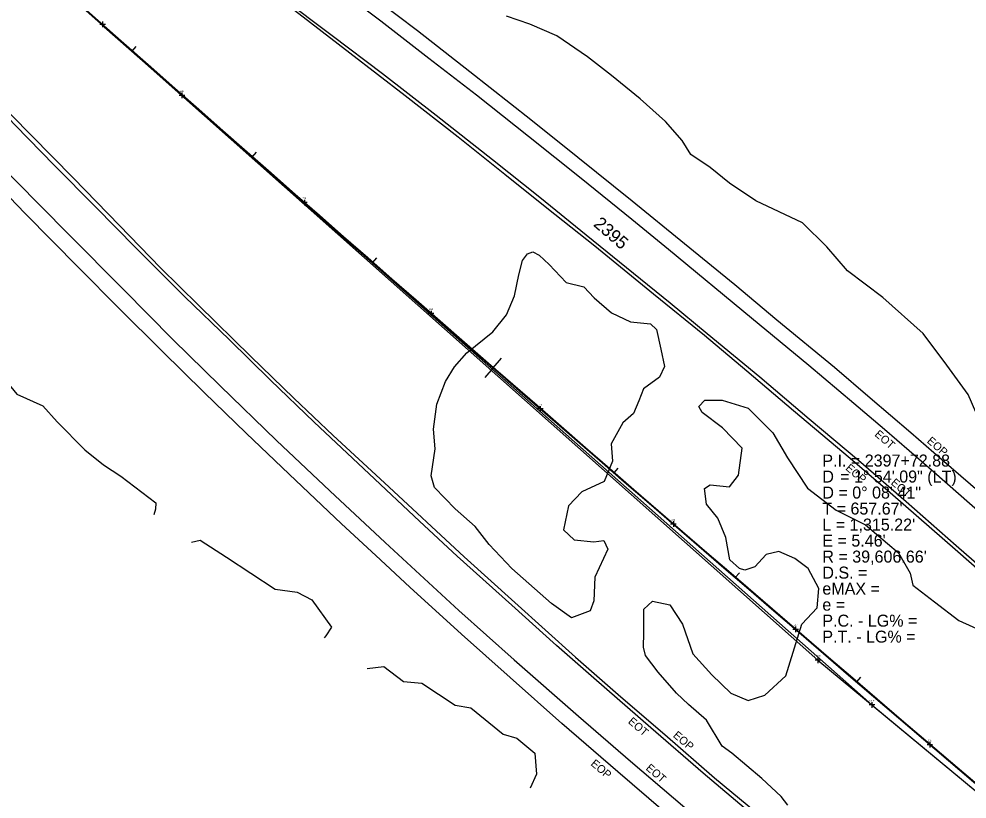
# Model space of a CAD drawing. Extents: x 2076109 to 2080761, y 592812 to 596750.
# Drawn here: x 2077921 to 2078513, y 594710 to 595198 of the extents above; entities that cross this region are included whole.
import ezdxf

# ---------------------------------------------------------------- set-up
doc = ezdxf.new("R2010")
doc.units = 0
for name, color, linetype in [('Default', 7, 'Continuous'), ('RD_EX_Misc', 7, 'Continuous'), ('RD_EX_Misc_txCode', 7, 'Continuous'), ('RD_EX_Road', 7, 'Continuous'), ('RD_EX_Road_txCode', 7, 'Continuous'), ('RD_EX_VEG', 7, 'Continuous'), ('RD_HC_Cl', 7, 'Continuous'), ('RD_HC_Data', 7, 'Continuous'), ('RD_HC_Data_Tic', 7, 'Continuous'), ('RD_HC_TX_Sta50', 7, 'Continuous')]:
    doc.layers.add(name, color=color, linetype=linetype)

msp = doc.modelspace()

# ---------------------------------------------------------------- linework, layer by layer
at = {"layer": 'Default'}
for p, q in [((2077364.31, 595733.06), (2078453.96, 594769.07)), ((2077364.31, 595733.06), (2078453.96, 594769.07)), ((2077404.89, 595698.18), (2078420.27, 594797.03)), ((2077404.89, 595698.18), (2078420.27, 594797.03)), ((2077975.19, 595194.17), (2077971.69, 595194.17)), ((2077975.19, 595194.17), (2077971.69, 595194.17)), ((2077973.44, 595195.92), (2077973.44, 595192.42)), ((2077973.44, 595195.92), (2077973.44, 595192.42)), ((2078024.71, 595149.76), (2078021.21, 595149.76)), ((2078024.71, 595149.76), (2078021.21, 595149.76)), ((2078022.96, 595151.51), (2078022.96, 595148.01)), ((2078022.96, 595151.51), (2078022.96, 595148.01)), ((2078099.45, 595084.6), (2078099.45, 595081.1)), ((2078099.45, 595084.6), (2078099.45, 595081.1)), ((2078101.2, 595082.85), (2078097.7, 595082.85)), ((2078101.2, 595082.85), (2078097.7, 595082.85)), ((2078180.32, 595013.58), (2078176.82, 595013.58)), ((2078180.32, 595013.58), (2078176.82, 595013.58)), ((2078178.57, 595015.33), (2078178.57, 595011.83)), ((2078178.57, 595015.33), (2078178.57, 595011.83)), ((2078248.58, 594953.95), (2078245.08, 594953.95)), ((2078248.58, 594953.95), (2078245.08, 594953.95)), ((2078246.83, 594955.7), (2078246.83, 594952.2)), ((2078246.83, 594955.7), (2078246.83, 594952.2)), ((2078329.94, 594883.79), (2078329.94, 594880.29)), ((2078329.94, 594883.79), (2078329.94, 594880.29)), ((2078331.69, 594882.04), (2078328.19, 594882.04)), ((2078331.69, 594882.04), (2078328.19, 594882.04)), ((2078406.28, 594818.04), (2078406.28, 594814.54)), ((2078406.28, 594818.04), (2078406.28, 594814.54)), ((2078408.03, 594816.29), (2078404.53, 594816.29)), ((2078408.03, 594816.29), (2078404.53, 594816.29)), ((2078422.02, 594797.03), (2078418.52, 594797.03)), ((2078422.02, 594797.03), (2078418.52, 594797.03)), ((2078422.02, 594797.03), (2078418.52, 594797.03)), ((2078422.02, 594797.03), (2078418.52, 594797.03)), ((2078420.27, 594798.78), (2078420.27, 594795.28)), ((2078420.27, 594798.78), (2078420.27, 594795.28)), ((2078420.27, 594798.78), (2078420.27, 594795.28)), ((2078420.27, 594798.78), (2078420.27, 594795.28)), ((2078420.27, 594797.03), (2079388.11, 593993.88)), ((2078420.27, 594797.03), (2079388.11, 593993.88)), ((2078453.96, 594770.82), (2078453.96, 594767.32)), ((2078453.96, 594770.82), (2078453.96, 594767.32)), ((2078453.96, 594770.82), (2078453.96, 594767.32)), ((2078453.96, 594770.82), (2078453.96, 594767.32)), ((2078455.71, 594769.07), (2078452.21, 594769.07)), ((2078455.71, 594769.07), (2078452.21, 594769.07)), ((2078455.71, 594769.07), (2078452.21, 594769.07)), ((2078455.71, 594769.07), (2078452.21, 594769.07)), ((2078453.96, 594769.07), (2079386.42, 593995.29)), ((2078453.96, 594769.07), (2079386.42, 593995.29)), ((2078491.88, 594744.27), (2078488.38, 594744.27)), ((2078491.88, 594744.27), (2078488.38, 594744.27)), ((2078490.13, 594746.02), (2078490.13, 594742.52)), ((2078490.13, 594746.02), (2078490.13, 594742.52))]:
    msp.add_line(p, q, dxfattribs=at)
for centre, radius, start, end in [((2104218.85, 624856.19), 39606.66, 228.410497, 230.313125), ((2104218.85, 624856.19), 39606.66, 228.410497, 230.313125), ((2104856.13, 625580.79), 40571.24, 228.501187, 230.313123), ((2104856.13, 625580.79), 40571.24, 228.501187, 230.313123)]:
    msp.add_arc(centre, radius, start, end, dxfattribs=at)
at = {"layer": 'RD_EX_Misc'}
for points in [[(2078547.92, 594865.99), (2078523.55, 594887.48), (2078492.6, 594914.58), (2078461.72, 594941.03), (2078442.57, 594957.36), (2078414.55, 594981.01), (2078378.82, 595010.71), (2078326.85, 595053.48), (2078303.99, 595072.33), (2078272.31, 595097.98), (2078239.48, 595124.07), (2078206.94, 595149.86), (2078177.28, 595172.92), (2078147.14, 595196.07), (2078111.31, 595223.33), (2078077.15, 595249.21), (2078034.45, 595281.85), (2078002.89, 595305.93), (2077949.74, 595346.22)], [(2078547.92, 594865.99), (2078523.55, 594887.48), (2078492.6, 594914.58), (2078461.72, 594941.03), (2078442.57, 594957.36), (2078414.55, 594981.01), (2078378.82, 595010.71), (2078326.85, 595053.48), (2078303.99, 595072.33), (2078272.31, 595097.98), (2078239.48, 595124.07), (2078206.94, 595149.86), (2078177.28, 595172.92), (2078147.14, 595196.07), (2078111.31, 595223.33), (2078077.15, 595249.21), (2078034.45, 595281.85), (2078002.89, 595305.93), (2077949.74, 595346.22)], [(2077948.94, 595314.49), (2077983.17, 595288.64), (2078019.77, 595260.72), (2078053.66, 595234.89), (2078085.02, 595211.3), (2078116.87, 595187.29), (2078148.23, 595163.42), (2078181.8, 595137.39), (2078217.02, 595109.84), (2078246.55, 595086.19), (2078275.57, 595062.75), (2078305.1, 595038.73), (2078327.94, 595020.19), (2078351.12, 595001.07), (2078383.9, 594974.11), (2078414.8, 594947.69), (2078445.52, 594921.98), (2078475.27, 594896.22), (2078506.67, 594868.78), (2078527.36, 594850.61)], [(2077948.94, 595314.49), (2077983.17, 595288.64), (2078019.77, 595260.72), (2078053.66, 595234.89), (2078085.02, 595211.3), (2078116.87, 595187.29), (2078148.23, 595163.42), (2078181.8, 595137.39), (2078217.02, 595109.84), (2078246.55, 595086.19), (2078275.57, 595062.75), (2078305.1, 595038.73), (2078327.94, 595020.19), (2078351.12, 595001.07), (2078383.9, 594974.11), (2078414.8, 594947.69), (2078445.52, 594921.98), (2078475.27, 594896.22), (2078506.67, 594868.78), (2078527.36, 594850.61)], [(2077812.69, 595205.74), (2077860.4, 595156.88), (2077885.59, 595131.05), (2077918.9, 595096.93), (2077951.97, 595063.28), (2077986.45, 595028.54), (2078017.36, 594997.38), (2078046.97, 594968.42), (2078082.15, 594934.23), (2078115.46, 594902.77), (2078149.86, 594870.52), (2078195.91, 594828.19), (2078230.53, 594797.18), (2078270.78, 594762.03), (2078303.08, 594733.97), (2078349.76, 594694.22), (2078384.22, 594665.44)], [(2077812.69, 595205.74), (2077860.4, 595156.88), (2077885.59, 595131.05), (2077918.9, 595096.93), (2077951.97, 595063.28), (2077986.45, 595028.54), (2078017.36, 594997.38), (2078046.97, 594968.42), (2078082.15, 594934.23), (2078115.46, 594902.77), (2078149.86, 594870.52), (2078195.91, 594828.19), (2078230.53, 594797.18), (2078270.78, 594762.03), (2078303.08, 594733.97), (2078349.76, 594694.22), (2078384.22, 594665.44)], [(2078402.59, 594681.19), (2078376.88, 594702.6), (2078348.66, 594726.55), (2078315.84, 594754.87), (2078280.23, 594785.85), (2078257.02, 594806.28), (2078229.05, 594831.44), (2078194.83, 594862.11), (2078171.35, 594883.78), (2078139.88, 594913.53), (2078105.56, 594945.66), (2078078.38, 594971.9), (2078052.44, 594997.28), (2078024.89, 595024.02), (2077994.25, 595054.58), (2077968.94, 595080.1), (2077943.23, 595106.24), (2077919, 595131.04), (2077898.15, 595152.63), (2077868.92, 595182.73), (2077850.7, 595201.63)], [(2078402.59, 594681.19), (2078376.88, 594702.6), (2078348.66, 594726.55), (2078315.84, 594754.87), (2078280.23, 594785.85), (2078257.02, 594806.28), (2078229.05, 594831.44), (2078194.83, 594862.11), (2078171.35, 594883.78), (2078139.88, 594913.53), (2078105.56, 594945.66), (2078078.38, 594971.9), (2078052.44, 594997.28), (2078024.89, 595024.02), (2077994.25, 595054.58), (2077968.94, 595080.1), (2077943.23, 595106.24), (2077919, 595131.04), (2077898.15, 595152.63), (2077868.92, 595182.73), (2077850.7, 595201.63)]]:
    msp.add_lwpolyline(points, dxfattribs=at)
at = {"layer": 'RD_EX_Road'}
for points in [[(2078558.22, 594869.34), (2078530.91, 594893.2), (2078521.67, 594901.52), (2078497.33, 594922.45), (2078478.18, 594939.06), (2078452.82, 594960.76), (2078430.65, 594979.76), (2078394.66, 595009.49), (2078368.3, 595031.41), (2078336.81, 595057.13), (2078304.21, 595083.71), (2078270.36, 595111.03), (2078240.97, 595134.51), (2078202.89, 595164.59), (2078170.15, 595190.09), (2078144.69, 595209.49), (2078118.53, 595229.54), (2078095.36, 595247.04), (2078066.11, 595268.74), (2078042.16, 595286.91), (2078005.38, 595314.83), (2077980.94, 595333.23), (2077970.95, 595340.99)], [(2078558.22, 594869.34), (2078530.91, 594893.2), (2078521.67, 594901.52), (2078497.33, 594922.45), (2078478.18, 594939.06), (2078452.82, 594960.76), (2078430.65, 594979.76), (2078394.66, 595009.49), (2078368.3, 595031.41), (2078336.81, 595057.13), (2078304.21, 595083.71), (2078270.36, 595111.03), (2078240.97, 595134.51), (2078202.89, 595164.59), (2078170.15, 595190.09), (2078144.69, 595209.49), (2078118.53, 595229.54), (2078095.36, 595247.04), (2078066.11, 595268.74), (2078042.16, 595286.91), (2078005.38, 595314.83), (2077980.94, 595333.23), (2077970.95, 595340.99)], [(2077952.98, 595309.03), (2077986.31, 595283.86), (2078021.67, 595256.91), (2078055.44, 595231.27), (2078085.91, 595208.57), (2078127.78, 595176.36), (2078162.35, 595149.71), (2078195.51, 595123.85), (2078224.64, 595100.6), (2078250.87, 595079.67), (2078280.9, 595055.74), (2078317.56, 595025.94), (2078349.29, 594999.96), (2078375.78, 594977.71), (2078405, 594953.04), (2078440.35, 594923.16), (2078465.28, 594901.73), (2078507.59, 594865.01), (2078528.26, 594846.85)], [(2077952.98, 595309.03), (2077986.31, 595283.86), (2078021.67, 595256.91), (2078055.44, 595231.27), (2078085.91, 595208.57), (2078127.78, 595176.36), (2078162.35, 595149.71), (2078195.51, 595123.85), (2078224.64, 595100.6), (2078250.87, 595079.67), (2078280.9, 595055.74), (2078317.56, 595025.94), (2078349.29, 594999.96), (2078375.78, 594977.71), (2078405, 594953.04), (2078440.35, 594923.16), (2078465.28, 594901.73), (2078507.59, 594865.01), (2078528.26, 594846.85)], [(2077854.91, 595200.66), (2077877.75, 595177.1), (2077904.18, 595149.75), (2077928.86, 595124.99), (2077955.23, 595098.06), (2077983.95, 595068.48), (2078009.65, 595042.17), (2078033.35, 595018.7), (2078066.05, 594986.67), (2078092.96, 594960.65), (2078117.38, 594937.31), (2078149.5, 594907.79), (2078199.33, 594861.59), (2078231.01, 594833.12), (2078268.85, 594798.92), (2078297.2, 594774.26), (2078324.57, 594750.57), (2078355.73, 594723.65), (2078382.01, 594701.63), (2078403.91, 594683.55)], [(2077854.91, 595200.66), (2077877.75, 595177.1), (2077904.18, 595149.75), (2077928.86, 595124.99), (2077955.23, 595098.06), (2077983.95, 595068.48), (2078009.65, 595042.17), (2078033.35, 595018.7), (2078066.05, 594986.67), (2078092.96, 594960.65), (2078117.38, 594937.31), (2078149.5, 594907.79), (2078199.33, 594861.59), (2078231.01, 594833.12), (2078268.85, 594798.92), (2078297.2, 594774.26), (2078324.57, 594750.57), (2078355.73, 594723.65), (2078382.01, 594701.63), (2078403.91, 594683.55)], [(2078373.49, 594660.86), (2078350.79, 594679.96), (2078323.49, 594703.04), (2078295.32, 594727.33), (2078260.34, 594757.49), (2078227.96, 594786.32), (2078197.61, 594813.23), (2078165.4, 594842.74), (2078144.08, 594862.48), (2078122.73, 594882.29), (2078089.93, 594913.22), (2078063.14, 594938.9), (2078036.94, 594964.31), (2078010.5, 594990.24), (2077983.8, 595016.72), (2077958.57, 595042.08), (2077925.08, 595076.09), (2077900.51, 595101.35), (2077873.61, 595129.01), (2077849.3, 595153.72), (2077820.29, 595183.84)], [(2078373.49, 594660.86), (2078350.79, 594679.96), (2078323.49, 594703.04), (2078295.32, 594727.33), (2078260.34, 594757.49), (2078227.96, 594786.32), (2078197.61, 594813.23), (2078165.4, 594842.74), (2078144.08, 594862.48), (2078122.73, 594882.29), (2078089.93, 594913.22), (2078063.14, 594938.9), (2078036.94, 594964.31), (2078010.5, 594990.24), (2077983.8, 595016.72), (2077958.57, 595042.08), (2077925.08, 595076.09), (2077900.51, 595101.35), (2077873.61, 595129.01), (2077849.3, 595153.72), (2077820.29, 595183.84)]]:
    msp.add_lwpolyline(points, dxfattribs=at)
at = {"layer": 'RD_EX_VEG'}
for points in [[(2078557.7, 594903.93), (2078543.39, 594912.86), (2078531.57, 594916.48), (2078520.77, 594933.39), (2078521.66, 594945.68), (2078514, 594963.05), (2078500.7, 594981.35), (2078485.99, 595001.02), (2078460.72, 595023.62), (2078438.61, 595040.22), (2078425.78, 595055.18), (2078410.65, 595070.25), (2078381.52, 595083.99), (2078365.03, 595095.08), (2078352.91, 595104.83), (2078340.83, 595112.9), (2078335.45, 595121.7), (2078324.96, 595133.57), (2078309.12, 595147.59), (2078291.24, 595162.24), (2078276.39, 595173.96), (2078257.26, 595186.92), (2078240.36, 595194.3), (2078225.66, 595199.27)], [(2078557.7, 594903.93), (2078543.39, 594912.86), (2078531.57, 594916.48), (2078520.77, 594933.39), (2078521.66, 594945.68), (2078514, 594963.05), (2078500.7, 594981.35), (2078485.99, 595001.02), (2078460.72, 595023.62), (2078438.61, 595040.22), (2078425.78, 595055.18), (2078410.65, 595070.25), (2078381.52, 595083.99), (2078365.03, 595095.08), (2078352.91, 595104.83), (2078340.83, 595112.9), (2078335.45, 595121.7), (2078324.96, 595133.57), (2078309.12, 595147.59), (2078291.24, 595162.24), (2078276.39, 595173.96), (2078257.26, 595186.92), (2078240.36, 595194.3), (2078225.66, 595199.27)], [(2077773.22, 595117.2), (2077791.56, 595101.41), (2077809.23, 595084.36), (2077830.79, 595059.77), (2077838.08, 595056.89), (2077849.16, 595042.68), (2077857.1, 595036.66), (2077867.15, 595031.61), (2077876.37, 595019.54), (2077892.53, 595000.28), (2077900.86, 594995.59), (2077906.78, 594987.42), (2077911.5, 594973.3), (2077919.86, 594963.24), (2077936.16, 594955.82), (2077945.1, 594946.01), (2077962.43, 594928.33), (2077974.01, 594919.03), (2077984.91, 594911.96), (2078006.62, 594895.34), (2078006.55, 594891.36), (2078005.4, 594887.74)], [(2077773.22, 595117.2), (2077791.56, 595101.41), (2077809.23, 595084.36), (2077830.79, 595059.77), (2077838.08, 595056.89), (2077849.16, 595042.68), (2077857.1, 595036.66), (2077867.15, 595031.61), (2077876.37, 595019.54), (2077892.53, 595000.28), (2077900.86, 594995.59), (2077906.78, 594987.42), (2077911.5, 594973.3), (2077919.86, 594963.24), (2077936.16, 594955.82), (2077945.1, 594946.01), (2077962.43, 594928.33), (2077974.01, 594919.03), (2077984.91, 594911.96), (2078006.62, 594895.34), (2078006.55, 594891.36), (2078005.4, 594887.74)], [(2078401.4, 594706.61), (2078397.2, 594711.83), (2078385.2, 594723.15), (2078366.44, 594738.92), (2078360.42, 594743.3), (2078350.66, 594759.51), (2078339.35, 594769.29), (2078331.82, 594776.43), (2078320.42, 594789.62), (2078312.6, 594799.89), (2078311.25, 594805.29), (2078311.43, 594814.15), (2078311.43, 594828.86), (2078316.99, 594833.87), (2078327.71, 594831.56), (2078335.64, 594819.48), (2078342.19, 594801.04), (2078353.99, 594787.88), (2078365.87, 594776.53), (2078376.59, 594771.83), (2078387.15, 594775.17), (2078400.18, 594787.25), (2078410.1, 594819.45), (2078419.8, 594829.77), (2078420.71, 594841.86), (2078414.04, 594854.34), (2078405.88, 594860.54), (2078395.8, 594864.89), (2078387.89, 594863.16), (2078380.76, 594855.43), (2078374.68, 594853.25), (2078371.21, 594854.36), (2078365.11, 594859.73), (2078362.69, 594873.74), (2078357.75, 594885.66), (2078350.69, 594894.43), (2078349.49, 594904.27), (2078352.98, 594906.64), (2078364.91, 594905.32), (2078370.58, 594912.63), (2078372.9, 594929.41), (2078360.54, 594942.12), (2078348.03, 594951.84), (2078345.76, 594955.43), (2078349.51, 594959.41), (2078360.34, 594959.39), (2078376.7, 594954.44), (2078392.05, 594938.99), (2078401.26, 594923.44), (2078413.71, 594904.58), (2078431.61, 594890.82), (2078450.05, 594881.58), (2078470.53, 594864.16), (2078477.92, 594851.44), (2078479.42, 594843.91), (2078493.14, 594833.53)], [(2078401.4, 594706.61), (2078397.2, 594711.83), (2078385.2, 594723.15), (2078366.44, 594738.92), (2078360.42, 594743.3), (2078350.66, 594759.51), (2078339.35, 594769.29), (2078331.82, 594776.43), (2078320.42, 594789.62), (2078312.6, 594799.89), (2078311.25, 594805.29), (2078311.43, 594814.15), (2078311.43, 594828.86), (2078316.99, 594833.87), (2078327.71, 594831.56), (2078335.64, 594819.48), (2078342.19, 594801.04), (2078353.99, 594787.88), (2078365.87, 594776.53), (2078376.59, 594771.83), (2078387.15, 594775.17), (2078400.18, 594787.25), (2078410.1, 594819.45), (2078419.8, 594829.77), (2078420.71, 594841.86), (2078414.04, 594854.34), (2078405.88, 594860.54), (2078395.8, 594864.89), (2078387.89, 594863.16), (2078380.76, 594855.43), (2078374.68, 594853.25), (2078371.21, 594854.36), (2078365.11, 594859.73), (2078362.69, 594873.74), (2078357.75, 594885.66), (2078350.69, 594894.43), (2078349.49, 594904.27), (2078352.98, 594906.64), (2078364.91, 594905.32), (2078370.58, 594912.63), (2078372.9, 594929.41), (2078360.54, 594942.12), (2078348.03, 594951.84), (2078345.76, 594955.43), (2078349.51, 594959.41), (2078360.34, 594959.39), (2078376.7, 594954.44), (2078392.05, 594938.99), (2078401.26, 594923.44), (2078413.71, 594904.58), (2078431.61, 594890.82), (2078450.05, 594881.58), (2078470.53, 594864.16), (2078477.92, 594851.44), (2078479.42, 594843.91), (2078493.14, 594833.53)], [(2078028.92, 594870.79), (2078034.33, 594871.93), (2078050.89, 594861.34), (2078081.21, 594841.44), (2078094.87, 594839.56), (2078104.21, 594834.75), (2078116.32, 594817.65), (2078112.78, 594812.19), (2078111.83, 594811.07)], [(2078028.92, 594870.79), (2078034.33, 594871.93), (2078050.89, 594861.34), (2078081.21, 594841.44), (2078094.87, 594839.56), (2078104.21, 594834.75), (2078116.32, 594817.65), (2078112.78, 594812.19), (2078111.83, 594811.07)], [(2078493.14, 594833.53), (2078508.15, 594821.8), (2078523.36, 594815.05)], [(2078493.14, 594833.53), (2078508.15, 594821.8), (2078523.36, 594815.05)], [(2078138.61, 594791.79), (2078149.1, 594793.07), (2078161.47, 594783.84), (2078172.8, 594782.66), (2078193.68, 594768.95), (2078203.34, 594767.35), (2078223.66, 594750.81), (2078232.1, 594748.41), (2078243.5, 594738.9), (2078244.44, 594725.96), (2078240.48, 594717.18)], [(2078138.61, 594791.79), (2078149.1, 594793.07), (2078161.47, 594783.84), (2078172.8, 594782.66), (2078193.68, 594768.95), (2078203.34, 594767.35), (2078223.66, 594750.81), (2078232.1, 594748.41), (2078243.5, 594738.9), (2078244.44, 594725.96), (2078240.48, 594717.18)]]:
    msp.add_lwpolyline(points, dxfattribs=at)
msp.add_lwpolyline([(2078252.4, 595044.16), (2078262.94, 595032.96), (2078274.08, 595030.28), (2078280.5, 595023.35), (2078291.3, 595013.99), (2078303.27, 595008.4), (2078315.7, 595007.02), (2078319.36, 595003.54), (2078322.15, 594991.24), (2078324.31, 594980.39), (2078321.27, 594973.79), (2078311.32, 594966.62), (2078308.46, 594958.94), (2078305.12, 594951.12), (2078298.34, 594945.31), (2078291.05, 594932.2), (2078291.93, 594921.34), (2078286.69, 594908.7), (2078272.67, 594902.26), (2078264.54, 594893.56), (2078261.28, 594878.49), (2078267.94, 594872.27), (2078280.18, 594870.88), (2078286.56, 594871.89), (2078288.99, 594866.32), (2078280.96, 594848.88), (2078280.17, 594834.11), (2078277.99, 594827.88), (2078266.42, 594823.56), (2078253.88, 594832.39), (2078229.06, 594854.23), (2078214.83, 594869.27), (2078206.07, 594880.59), (2078193.66, 594891.51), (2078180.65, 594904.96), (2078178.57, 594912.25), (2078181.09, 594929.04), (2078180.19, 594941.39), (2078182.11, 594957.04), (2078187.52, 594971.19), (2078193.24, 594980.3), (2078200.99, 594988.97), (2078217.12, 595002.1), (2078225.79, 595012.74), (2078230.7, 595024.56), (2078233.42, 595037.69), (2078235.77, 595046.73), (2078238.82, 595050.75), (2078242.1, 595052.01), (2078246.04, 595049.94)], close=True, dxfattribs=at)
msp.add_lwpolyline([(2078252.4, 595044.16), (2078262.94, 595032.96), (2078274.08, 595030.28), (2078280.5, 595023.35), (2078291.3, 595013.99), (2078303.27, 595008.4), (2078315.7, 595007.02), (2078319.36, 595003.54), (2078322.15, 594991.24), (2078324.31, 594980.39), (2078321.27, 594973.79), (2078311.32, 594966.62), (2078308.46, 594958.94), (2078305.12, 594951.12), (2078298.34, 594945.31), (2078291.05, 594932.2), (2078291.93, 594921.34), (2078286.69, 594908.7), (2078272.67, 594902.26), (2078264.54, 594893.56), (2078261.28, 594878.49), (2078267.94, 594872.27), (2078280.18, 594870.88), (2078286.56, 594871.89), (2078288.99, 594866.32), (2078280.96, 594848.88), (2078280.17, 594834.11), (2078277.99, 594827.88), (2078266.42, 594823.56), (2078253.88, 594832.39), (2078229.06, 594854.23), (2078214.83, 594869.27), (2078206.07, 594880.59), (2078193.66, 594891.51), (2078180.65, 594904.96), (2078178.57, 594912.25), (2078181.09, 594929.04), (2078180.19, 594941.39), (2078182.11, 594957.04), (2078187.52, 594971.19), (2078193.24, 594980.3), (2078200.99, 594988.97), (2078217.12, 595002.1), (2078225.79, 595012.74), (2078230.7, 595024.56), (2078233.42, 595037.69), (2078235.77, 595046.73), (2078238.82, 595050.75), (2078242.1, 595052.01), (2078246.04, 595049.94)], close=True, dxfattribs=at)
at = {"layer": 'RD_HC_Cl'}
msp.add_arc((2104218.85, 624856.19), 39606.66, 228.410497, 230.313125, dxfattribs=at)
msp.add_arc((2104218.85, 624856.19), 39606.66, 228.410497, 230.313125, dxfattribs=at)
at = {"layer": 'RD_HC_Data_Tic'}
for p, q in [((2077991.86, 595177.37), (2077994.5, 595180.37)), ((2077991.86, 595177.37), (2077994.5, 595180.37)), ((2078066.87, 595111.25), (2078069.51, 595114.25)), ((2078066.87, 595111.25), (2078069.51, 595114.25)), ((2078142.06, 595045.31), (2078144.69, 595048.32)), ((2078142.06, 595045.31), (2078144.69, 595048.32)), ((2078217.41, 594979.57), (2078222.66, 594985.6)), ((2078217.41, 594979.57), (2078222.66, 594985.6)), ((2078217.41, 594979.57), (2078212.16, 594973.53)), ((2078217.41, 594979.57), (2078212.16, 594973.53)), ((2078292.92, 594914.01), (2078295.54, 594917.04)), ((2078292.92, 594914.01), (2078295.54, 594917.04)), ((2078368.6, 594848.65), (2078371.22, 594851.68)), ((2078368.6, 594848.65), (2078371.22, 594851.68)), ((2078444.45, 594783.48), (2078447.05, 594786.52)), ((2078444.45, 594783.48), (2078447.05, 594786.52))]:
    msp.add_line(p, q, dxfattribs=at)

# ---------------------------------------------------------------- texts
at = {"layer": 'Default'}
for s, p in [('232', (2078021.78, 595151.96)), ('232', (2078021.78, 595151.96)), ('233', (2078098.27, 595085.05)), ('233', (2078098.27, 595085.05)), ('234', (2078177.39, 595015.78)), ('234', (2078177.39, 595015.78)), ('235', (2078245.65, 594956.15)), ('235', (2078245.65, 594956.15)), ('236', (2078328.74, 594884.24)), ('236', (2078328.74, 594884.24)), ('237', (2078405.1, 594818.49)), ('237', (2078405.1, 594818.49)), ('25005', (2078418.11, 594799.23)), ('25005', (2078418.11, 594799.23)), ('20005', (2078451.76, 594771.27)), ('20005', (2078451.76, 594771.27)), ('238', (2078488.95, 594746.47)), ('238', (2078488.95, 594746.47))]:
    msp.add_text(s, height=1, dxfattribs=at).set_placement(p)
at = {"layer": 'RD_EX_Misc_txCode'}
for p in [(2078455.26, 594937.53), (2078455.26, 594937.53), (2078465.41, 594907.3), (2078465.41, 594907.3), (2078301.25, 594758.16), (2078301.25, 594758.16), (2078312.34, 594729.05), (2078312.34, 594729.05)]:
    msp.add_text('EOT', height=5, rotation=319.16753, dxfattribs=at).set_placement(p)
at = {"layer": 'RD_EX_Road_txCode'}
for p in [(2078487.94, 594933.36), (2078487.94, 594933.36), (2078437.1, 594916.39), (2078437.1, 594916.39), (2078329.37, 594749.5), (2078329.37, 594749.5), (2078277.94, 594731.84), (2078277.94, 594731.84)]:
    msp.add_text('EOP', height=5, rotation=319.16753, dxfattribs=at).set_placement(p)
at = {"layer": 'RD_HC_Data'}
for s, p in [('P.I. = 2397+72.88', (2078423, 594918)), ('P.I. = 2397+72.88', (2078423, 594918)), ('D', (2078423, 594908)), ('D', (2078423, 594908)), ('    = 1%%d 54\' 09" (LT)', (2078423, 594908)), ('    = 1%%d 54\' 09" (LT)', (2078423, 594908)), ('D = 0%%d 08\' 41"', (2078423, 594898)), ('D = 0%%d 08\' 41"', (2078423, 594898)), ("T = 657.67'", (2078423, 594888)), ("T = 657.67'", (2078423, 594888)), ("L = 1,315.22'", (2078423, 594878)), ("L = 1,315.22'", (2078423, 594878)), ("E = 5.46'", (2078423, 594868)), ("E = 5.46'", (2078423, 594868)), ("R = 39,606.66'", (2078423, 594858)), ("R = 39,606.66'", (2078423, 594858)), ('D.S. = ', (2078423, 594848)), ('D.S. = ', (2078423, 594848)), ('eMAX = ', (2078423, 594838)), ('eMAX = ', (2078423, 594838)), ('e = ', (2078423, 594828)), ('e = ', (2078423, 594828)), ('P.C. - LG% = ', (2078423, 594818)), ('P.C. - LG% = ', (2078423, 594818)), ('P.T. - LG% = ', (2078423, 594808)), ('P.T. - LG% = ', (2078423, 594808))]:
    msp.add_text(s, height=7.5, dxfattribs=at).set_placement(p)
at = {"layer": 'RD_HC_TX_Sta50'}
msp.add_text('2395', height=8, rotation=318.96714, dxfattribs=at).set_placement((2078279.53, 595068.67))
msp.add_text('2395', height=8, rotation=318.96714, dxfattribs=at).set_placement((2078279.53, 595068.67))

doc.saveas('drawing.dxf')
